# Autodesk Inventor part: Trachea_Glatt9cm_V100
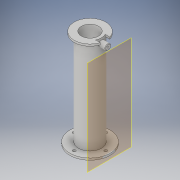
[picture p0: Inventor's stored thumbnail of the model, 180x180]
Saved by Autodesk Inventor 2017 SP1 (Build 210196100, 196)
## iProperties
Part Number: Trachea_Glatt9cm_V100
Material: Generisch
Document SubType Name: Modeling
Designer: haesner
Density: 1 g/cm^3
Appearance: Vorgabe
Part Number: Trachea_Glatt10cm_V100_3D-Druck
Author: haesner
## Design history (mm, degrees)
sketch "Skizze1"
  geometry: C1 r 9 at (0, 0); C2 r 21 at (0, 0); 1 further point
  constraints: 2 centre point, 2 coincident
  dimensions: "d0" = 18 diameter of C1; "d1" = 42 diameter of C2
extrude "Extrusion1" new body sketch "Skizze1" distance "d2" = 2; taper "d3" = 0 deg
sketch "Skizze2"
  geometry: C1 r 9 at (0, 0) reference; C2 r 12 at (0, 0); 1 further point
  constraints: 1 centre point, 1 coincident
  dimensions: "d4" = 24 diameter of C2
extrude "Extrusion2" join sketch "Skizze2" distance "d5" = 100; taper "d6" = 0 deg
sketch "Skizze3"
  geometry: L1 (7.483, 5)-(15.724, 5); L2 (31.664, 5)-(31.664, -5); L3 (15.724, -5)-(7.483, -5); L4 (0, -29.4)-(0, 29.4) reference; L5 (-31.533, 0)-(42.197, 0) reference; A1 r 16.5 centre (0, 0) between (15.724, 5) and (15.724, -5); A2 r 9 centre (0, 0) between (7.483, 5) and (7.483, -5) reference; 1 further point
  constraints: 6 end point, 4 point on circle, 1 centre point, 1 coincident, 1 horizontal, 1 parallel, 1 perpendicular, 1 other
  dimensions: "d7" = 33 diameter of A1; "d29" = 10 distance between parallel lines of L3 L1
extrude "Extrusion3" join sketch "Skizze3" distance "d8" = 2; taper "d9" = 0 deg
sketch "Skizze4"
  geometry: L1 (16.5, 0)-(0, 16.5); L2 (0, 16.5)-(-16.5, 0); L3 (-16.5, 0)-(0, -16.5); L4 (0, -16.5)-(16.5, 0); L5 (29.4, 0)-(-29.4, 0) reference; L6 (0, -29.4)-(0, 29.4) reference; 1 further point
  constraints: 8 end point, 3 point on line, 2 parallel, 2 perpendicular
  dimensions: "d10" = 16.5 distance from line of L6 L1.start
hole "Bohrung1" sketch "Skizze4" at (16.5, 0), (0, -16.5), (-16.5, 0), (0, 16.5) diameter "d11" = 3; stored, may be unused: countersink angle "d15" = 90 deg, drill point angle "d17" = 118 deg; dims "d12" = 6, "d13" = 4, "d14" = 2, "d16" = 8
workplane "Arbeitsebene1"
sketch "Skizze5"
  geometry: L1 (0, -20)-(0, 120) reference; L2 (-4.2, 0)-(4.2, 0) reference; C1 r 3 at (0, 97); 1 further point
  constraints: 1 centre point, 1 point on line
  dimensions: "d19" = 6 diameter of C1; "d20" = 97 distance from line of L2 C1.centre
extrude "Extrusion4" cut sketch "Skizze5" distance "d21" = 9; taper "d22" = 0 deg
sketch "Skizze6"
  geometry: C1 r 3 at (0, 0) reference; 1 further point
extrude "Extrusion5" join sketch "Skizze6" distance "d23" = 8; taper "d24" = 0 deg
sketch "Skizze7"
  geometry: C1 r 3 at (0, 0) reference; C2 r 0.75 at (0, 0); 1 further point
  constraints: 1 centre point, 1 coincident
  dimensions: "d25" = 1.5 diameter of C2
extrude "Extrusion6" cut sketch "Skizze7" distance "d26" = 18; taper "d27" = 0 deg
fillet "Rundung1" dims "d28" = 0.5
node "Volumenkörper1"
node "Projizierte Kontur1"
node "Projizierte Kontur2"
